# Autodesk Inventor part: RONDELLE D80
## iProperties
Created: 2004-11
Part Number: RONDELLE D80
Document SubType Name: Modeling
Designer: Bruno
Manufacturer: Standard
Standards Organization: Custom
Author: Bruno
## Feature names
1. Base1
